(* Logix 5000 project; controller AMCI_3204_generic_sample_RSLogix_V28 vendor 1 type 14 code 92 rev 28.11; software revision 28.00 *)

TASK MainTask (continuous, watchdog 500 ms) : MainProgram

MODULES
   Local : vendor 1 type 14 code 92 (ICP 0, rev 28.11)
      AMCI_3204 : vendor 1 type 0 code 15 (ICP 4, rev 1.1, Output RPI 5 ms)
           Local:4:O.Data[10]   // AMCI 3204 channel 3 command word
           Local:4:O.Data[15]   // AMCI 3204 channel 4 command word
           Local:4:O.Data[0]   // AMCI 3204 channel 1 command word
           Local:4:O.Data[5]   // AMCI 3204 channel 2 command word
           Local:4:I.Data[0].0   // Set when 3204 channel 1 CW motion occurring
           Local:4:I.Data[0].1   // set when 3204 channel 1 CCW motion is occurring
           Local:4:I.Data[0].7   // AMCI 3204 channel 1 move complete bit
           Local:4:I.Data[1]   // AMCI 3202 ch 1 current position data
           Local:4:I.Data[0].28   // Set when AMCI 3204 ch 1 is disabled
           Local:4:I.Data[0].10   // AMCI 3204 ch 1 position invalid bit
           Local:4:I.Data[0].13   // Set when AMCI 3204 ch 1 has a configuration error
           Local:4:I.Data[0].31   // AMCI 3204 ch 1 mode bit 1=config mode 0=command mode
END_MODULES

VAR_GLOBAL   (* controller tags *)
   blend_data_3204_ch1 : DINT[52];
        [12]   // Segment 3 Acceleration or Deceleration
        [11]   // Segment 3 speed
        [9]   // Segment 2 Acceleration or Deceleration
        [1]   // Number of Segments
        [3]   // Final Segment's Deceleration Value and Type
        [13]   // Segment 4 length
        [15]   // Segment 4 Acceleration or Deceleration
        [17]   // Segment 5 speed
        [5]   // Segment 1 speed
        [7]   // Segment 2 length
        [10]   // Segment 3 length
        [14]   // Segment 4 speed
        [16]   // Segment 5 length
        [18]   // Segment 5 Acceleraiton or Deceleration
        [0]   // channel number (1 or 2)
        [2]   // Acceleration Type
        [4]   // Segment 1 length
        [6]   // Segment 1 Acceleration or Deceleration
        [8]   // Segment 2 speed
   blend_message_3204_ch1 : MESSAGE;
        .DN   // set when blend data has been programmed
        MessageParameters(ServiceCode := 16#004c, LocalElement := blend_data_3204_ch1[0], ...)
   blend_run_CW_3204 : DINT[5] := ([0] := 4096);
        [0]   // command word to run blend profile CW
   buffered_3204_data : DINT[20];
        [10].31   // AMCI 3204 ch 3 mode bit 1=config mode 0=command mode
        [0].1   // set when CCW motion is occurring on ch 1 of the AMCI 3204 module
        [10].13   // set when AMCI 3204 ch 3 has a configuration error
        [15].13   // set when AMCI 3204 ch 4 has a configuration error
        [15].31   // AMCI 3204 ch 4 mode bit 1=config mode 0=command mode
        [0].0   // set when CW motion is occurring on ch 1 of the AMCI 3204 module
        [0].7   // AMCI 3204 move complete bit
        [15].0   // set when CW motion is occurring on ch 4 of the AMCI 3204 module
        [15].1   // set when CCW motion is occurring on ch 4 of the AMCI 3204 module
        [0].28   // set when AMCI 3204 ch 1 is disabled
        [5].28   // set when AMCI 3204 ch 2 is disabled
        [10].28   // Set when 3204 channel 3 is disabled
        [15].28   // Set when 3204 channel 4 is disabled
        [5].0   // set when CW motion is occurring on ch 2 of the AMCI 3204 module
        [5].1   // set when CCW motion is occurring on ch 2 of the AMCI 3204 module
        [10].0   // set when CW motion is occurring on ch 3 of the AMCI 3204 module
        [0].10   // AMCI 3204 ch 1 position invalid bit
        [10].1   // set when CCW motion is occurring on ch 3 of the AMCI 3204 module
        [0].13   // set when AMCI 3204 ch 1 has a configuration error
        [0].31   // AMCI 3204 ch 1 mode bit 1=config mode 0=command mode
        [5].13   // set when AMCI 3204 ch 2 has a configuration error
        [5].31   // AMCI 3204 ch 2 mode bit 1=config mode 0=command mode
   CCW_manual_move_3204_ch1 : DINT[5] := ([0] := 256, [2] := 2200, [3] := 10000, [4] := 10000);
   ch1_manual_move_occurring_CCW : BOOL;
   ch1_manual_move_occurring_CW : BOOL;
   ch2_manual_move_occurring_CCW : BOOL;
   ch2_manual_move_occurring_CW : BOOL;
   ch3_manual_move_occurring_CCW : BOOL;
   ch3_manual_move_occurring_CW : BOOL;
   ch4_manual_move_occurring_CCW : BOOL;
   ch4_manual_move_occurring_CW : BOOL;
   comment : INT;
   configure_3204_ch1 : DINT[5] := ([0] := -2146500561, [1] := 100);
        [1]   // starting speed
        [0]   // configuration word
   configure_3204_ch2 : DINT[5] := ([0] := -2146500561, [1] := 100);
        [1]   // starting speed
        [0]   // configuration word
   configure_3204_ch3 : DINT[5] := ([0] := -2146500561, [1] := 100);
        [0]   // configuration word
        [1]   // starting speed
   configure_3204_ch4 : DINT[5] := ([0] := -2146500561, [1] := 100);
        [0]   // configuration word
        [1]   // starting speed
   CW_manual_move_3204_ch1 : DINT[5] := ([0] := 128, [2] := 1500, [3] := 10000, [4] := 10000);
   CW_manual_move_3204_ch2 : DINT[5] := ([0] := 128, [2] := 1500, [3] := 10000, [4] := 10000);
   CW_manual_move_3204_ch3 : DINT[5] := ([0] := 128, [2] := 1500, [3] := 10000, [4] := 10000);
   CW_manual_move_3204_ch4 : DINT[5] := ([0] := 128, [2] := 1500, [3] := 10000, [4] := 10000);
   Home_CW_3204_ch1 : DINT[5] := ([0] := 32, [2] := 1000, [3] := 10000, [4] := 10000);
   one_shot : INT;
   preset_3204_ch1 : DINT[5] := ([0] := 512);
        [0]   // preset current position command word
   Relative_move_3204_ch1 : DINT[5] := ([0] := 2, [1] := 5000, [2] := 2000, [3] := 10000, [4] := 10000);
        [0]   // relative move command word
        [1]   // distance in pulses
        [2]   // speed in pulses/sec
        [4]   // deceleration in pulses/sec/sec
        [3]   // acceleration in pulses/sec/sec
   Relative_move_3204_ch2 : DINT[5] := ([0] := 2, [1] := 5000, [2] := 2000, [3] := 10000, [4] := 10000);
        [1]   // distance in pulses
        [3]   // acceleration in pulses/sec/sec
        [4]   // deceleration in pulses/sec/sec
        [2]   // speed in pulses/sec
        [0]   // relative move command word
   Relative_move_3204_ch3 : DINT[5] := ([0] := 2, [1] := 5000, [2] := 2000, [3] := 10000, [4] := 10000);
        [1]   // distance in pulses
        [2]   // speed in pulses/sec
        [4]   // deceleration in pulses/sec/sec
        [3]   // acceleration in pulses/sec/sec
        [0]   // relative move command word
   Relative_move_3204_ch4 : DINT[5] := ([0] := 2, [1] := 5000, [2] := 2000, [3] := 10000, [4] := 10000);
        [1]   // distance in pulses
        [2]   // speed in pulses/sec
        [4]   // deceleration in pulses/sec/sec
        [3]   // acceleration in pulses/sec/sec
        [0]   // relative move command word
   Reset_errors_3204 : DINT[5] := ([0] := 2048);
   run_3204_ch1 : INT;   // 1=run relative move 2=CW Manual Move 3=CCW Manual Move 4=Reset Errors 5=Home CW 6=Preset 7=Program Blend 8=Run Blend CW
   run_3204_ch2 : INT;   // 1=run relative move 2=CW Manual Move 3=CCW Manual Move 4=Reset Errors 5=Home CW 6=Preset 7=Program Blend 8=Run Blend CW
   run_3204_ch3 : INT;   // 1=run relative move 2=CW Manual Move 3=CCW Manual Move 4=Reset Errors 5=Home CW 6=Preset 7=Program Blend 8=Run Blend CW
   run_3204_ch4 : INT;   // 1=run relative move 2=CW Manual Move 3=CCW Manual Move 4=Reset Errors 5=Home CW 6=Preset 7=Program Blend 8=Run Blend CW
END_VAR

PROGRAM MainProgram   (* main routine MainRoutine *)

ROUTINE Channel_1_3204   (* ladder *)
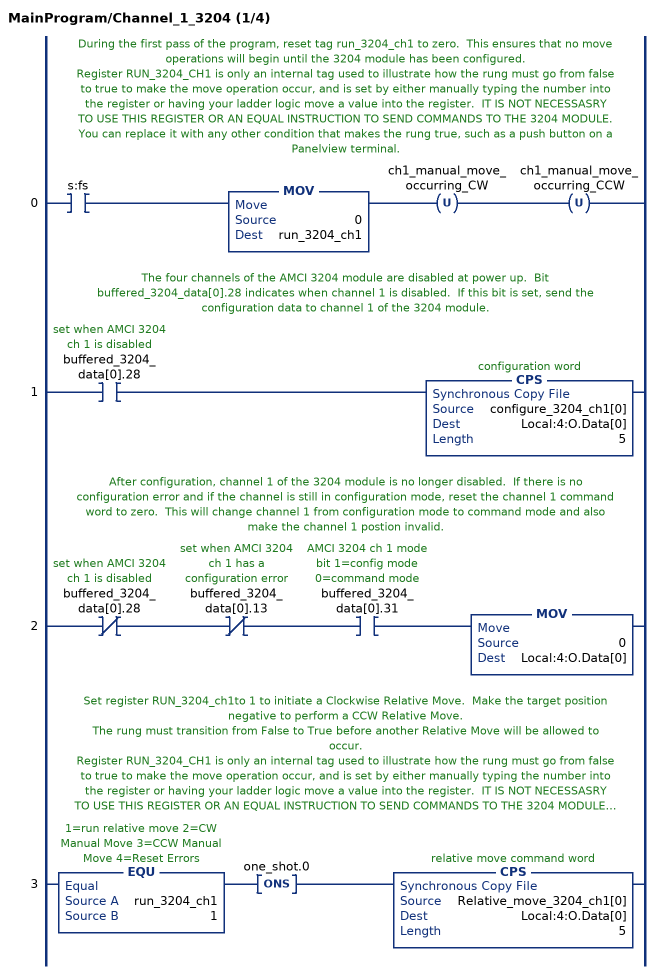
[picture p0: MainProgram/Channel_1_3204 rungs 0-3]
   // During the first pass of the program, reset tag run_3204_ch1 to zero.  This ensures that no move operations will begin until the 3204 module has been configured.
   // Register RUN_3204_CH1 is only an internal tag used to illustrate how the rung must go from false to true to make the move operation occur, and is set by either manually typing the number into the register or having your ladder logic move a value into the register.  IT IS NOT NECESSASRY TO USE THIS REGISTER OR AN EQUAL INSTRUCTION TO SEND COMMANDS TO THE 3204 MODULE.  You can replace it with any other condition that makes the rung true, such as a push button on a Panelview terminal.
   0: XIC(s:fs)MOV(0,run_3204_ch1)OTU(ch1_manual_move_occurring_CW)OTU(ch1_manual_move_occurring_CCW);
   // The four channels of the AMCI 3204 module are disabled at power up.  Bit buffered_3204_data[0].28 indicates when channel 1 is disabled.  If this bit is set, send the configuration data to channel 1 of the 3204 module.
   1: XIC(buffered_3204_data[0].28)CPS(configure_3204_ch1[0],Local:4:O.Data[0],5);
   // After configuration, channel 1 of the 3204 module is no longer disabled.  If there is no configuration error and if the channel is still in configuration mode, reset the channel 1 command word to zero.  This will change channel 1 from configuration mode to command mode and also make the channel 1 postion invalid.
   2: XIO(buffered_3204_data[0].28)XIO(buffered_3204_data[0].13)XIC(buffered_3204_data[0].31)MOV(0,Local:4:O.Data[0]);
   // Set register RUN_3204_ch1to 1 to initiate a Clockwise Relative Move.  Make the target position negative to perform a CCW Relative Move.
   // The rung must transition from False to True before another Relative Move will be allowed to occur.
   // Register RUN_3204_CH1 is only an internal tag used to illustrate how the rung must go from false to true to make the move operation occur, and is set by either manually typing the number into the register or having your ladder logic move a value into the register.  IT IS NOT NECESSASRY TO USE THIS REGISTER OR AN EQUAL INSTRUCTION TO SEND COMMANDS TO THE 3204 MODULE.  You can replace it with any other condition that makes the rung true, such as a push button on a Panelview terminal.
   3: EQU(run_3204_ch1,1)ONS(one_shot.0)CPS(Relative_move_3204_ch1[0],Local:4:O.Data[0],5);
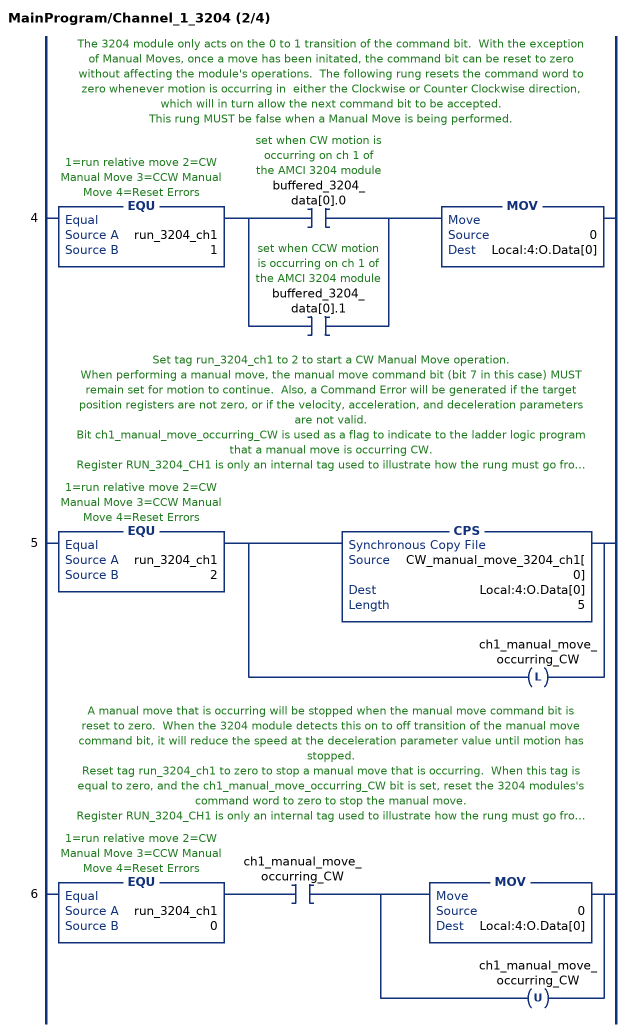
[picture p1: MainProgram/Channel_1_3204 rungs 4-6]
   // The 3204 module only acts on the 0 to 1 transition of the command bit.  With the exception of Manual Moves, once a move has been initated, the command bit can be reset to zero without affecting the module's operations.  The following rung resets the command word to zero whenever motion is occurring in  either the Clockwise or Counter Clockwise direction, which will in turn allow the next command bit to be accepted.
   // This rung MUST be false when a Manual Move is being performed.
   4: EQU(run_3204_ch1,1)[XIC(buffered_3204_data[0].0) ,XIC(buffered_3204_data[0].1) ]MOV(0,Local:4:O.Data[0]);
   // Set tag run_3204_ch1 to 2 to start a CW Manual Move operation.
   // When performing a manual move, the manual move command bit (bit 7 in this case) MUST remain set for motion to continue.  Also, a Command Error will be generated if the target position registers are not zero, or if the velocity, acceleration, and deceleration parameters are not valid.
   // Bit ch1_manual_move_occurring_CW is used as a flag to indicate to the ladder logic program that a manual move is occurring CW.
   // Register RUN_3204_CH1 is only an internal tag used to illustrate how the rung must go from false to true to make the move operation occur, and is set by either manually typing the number into the register or having your ladder logic move a value into the register.  IT IS NOT NECESSASRY TO USE THIS REGISTER OR AN EQUAL INSTRUCTION TO SEND COMMANDS TO THE 3204 MODULE.  You can replace it with any other condition that makes the rung true, such as a push button on a Panelview terminal.
   5: EQU(run_3204_ch1,2)[CPS(CW_manual_move_3204_ch1[0],Local:4:O.Data[0],5) ,OTL(ch1_manual_move_occurring_CW) ];
   // A manual move that is occurring will be stopped when the manual move command bit is reset to zero.  When the 3204 module detects this on to off transition of the manual move command bit, it will reduce the speed at the deceleration parameter value until motion has stopped.
   // Reset tag run_3204_ch1 to zero to stop a manual move that is occurring.  When this tag is equal to zero, and the ch1_manual_move_occurring_CW bit is set, reset the 3204 modules's command word to zero to stop the manual move.
   // Register RUN_3204_CH1 is only an internal tag used to illustrate how the rung must go from false to true to make the move operation occur, and is set by either manually typing the number into the register or having your ladder logic move a value into the register.  IT IS NOT NECESSASRY TO USE THIS REGISTER OR AN EQUAL INSTRUCTION TO SEND COMMANDS TO THE 3204 MODULE.  You can replace it with any other condition that makes the rung true, such as a push button on a Panelview terminal.
   6: EQU(run_3204_ch1,0)XIC(ch1_manual_move_occurring_CW)[MOV(0,Local:4:O.Data[0]) ,OTU(ch1_manual_move_occurring_CW) ];
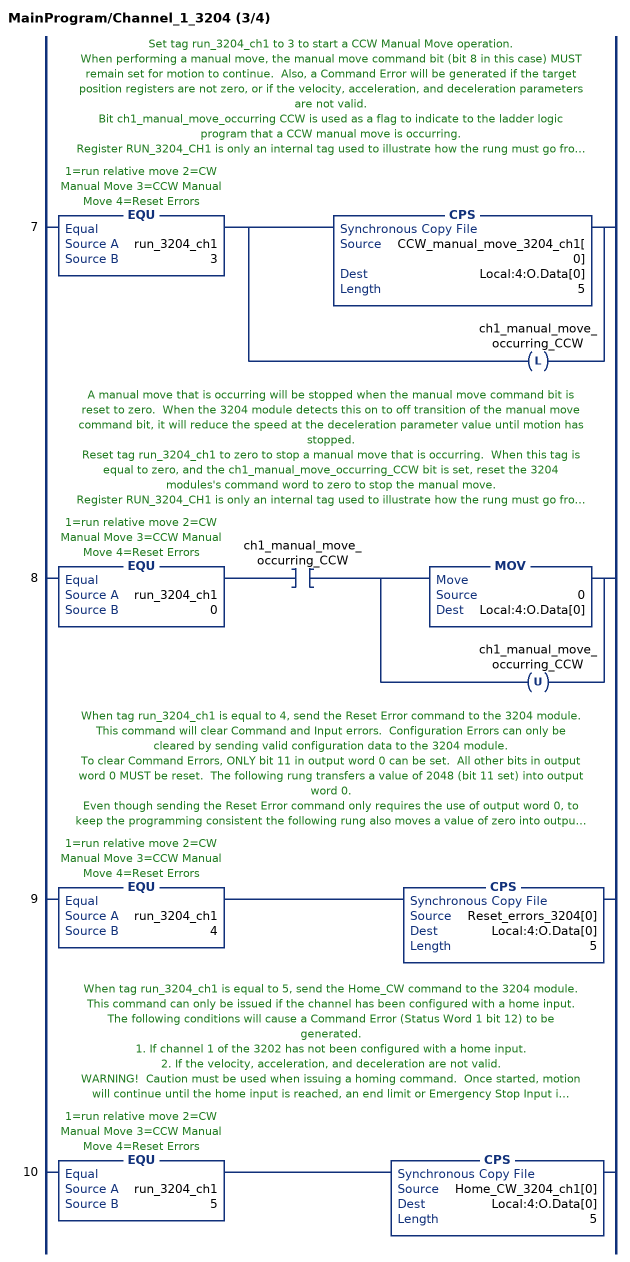
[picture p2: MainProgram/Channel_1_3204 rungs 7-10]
   // Set tag run_3204_ch1 to 3 to start a CCW Manual Move operation.
   // When performing a manual move, the manual move command bit (bit 8 in this case) MUST remain set for motion to continue.  Also, a Command Error will be generated if the target position registers are not zero, or if the velocity, acceleration, and deceleration parameters are not valid.
   // Bit ch1_manual_move_occurring CCW is used as a flag to indicate to the ladder logic program that a CCW manual move is occurring.
   // Register RUN_3204_CH1 is only an internal tag used to illustrate how the rung must go from false to true to make the move operation occur, and is set by either manually typing the number into the register or having your ladder logic move a value into the register.  IT IS NOT NECESSASRY TO USE THIS REGISTER OR AN EQUAL INSTRUCTION TO SEND COMMANDS TO THE 3204 MODULE.  You can replace it with any other condition that makes the rung true, such as a push button on a Panelview terminal.
   7: EQU(run_3204_ch1,3)[CPS(CCW_manual_move_3204_ch1[0],Local:4:O.Data[0],5) ,OTL(ch1_manual_move_occurring_CCW) ];
   // A manual move that is occurring will be stopped when the manual move command bit is reset to zero.  When the 3204 module detects this on to off transition of the manual move command bit, it will reduce the speed at the deceleration parameter value until motion has stopped.
   // Reset tag run_3204_ch1 to zero to stop a manual move that is occurring.  When this tag is equal to zero, and the ch1_manual_move_occurring_CCW bit is set, reset the 3204 modules's command word to zero to stop the manual move.
   // Register RUN_3204_CH1 is only an internal tag used to illustrate how the rung must go from false to true to make the move operation occur, and is set by either manually typing the number into the register or having your ladder logic move a value into the register.  IT IS NOT NECESSASRY TO USE THIS REGISTER OR AN EQUAL INSTRUCTION TO SEND COMMANDS TO THE 3204 MODULE.  You can replace it with any other condition that makes the rung true, such as a push button on a Panelview terminal.
   8: EQU(run_3204_ch1,0)XIC(ch1_manual_move_occurring_CCW)[MOV(0,Local:4:O.Data[0]) ,OTU(ch1_manual_move_occurring_CCW) ];
   // When tag run_3204_ch1 is equal to 4, send the Reset Error command to the 3204 module.  This command will clear Command and Input errors.  Configuration Errors can only be cleared by sending valid configuration data to the 3204 module.
   // To clear Command Errors, ONLY bit 11 in output word 0 can be set.  All other bits in output word 0 MUST be reset.  The following rung transfers a value of 2048 (bit 11 set) into output word 0.
   // Even though sending the Reset Error command only requires the use of output word 0, to keep the programming consistent the following rung also moves a value of zero into output words 1 through 4.
   // Register RUN_3204_CH1 is only an internal tag used to illustrate how the rung must go from false to true to make the move operation occur, and is set by either manually typing the number into the register or having your ladder logic move a value into the register.  IT IS NOT NECESSASRY TO USE THIS REGISTER OR AN EQUAL INSTRUCTION TO SEND COMMANDS TO THE 3204 MODULE.  You can replace it with any other condition that makes the rung true, such as a push button on a Panelview terminal.
   9: EQU(run_3204_ch1,4)CPS(Reset_errors_3204[0],Local:4:O.Data[0],5);
   // When tag run_3204_ch1 is equal to 5, send the Home_CW command to the 3204 module.  This command can only be issued if the channel has been configured with a home input.  The following conditions will cause a Command Error (Status Word 1 bit 12) to be generated.
   // 1. If channel 1 of the 3202 has not been configured with a home input.
   // 2. If the velocity, acceleration, and deceleration are not valid.
   // WARNING!  Caution must be used when issuing a homing command.  Once started, motion will continue until the home input is reached, an end limit or Emergency Stop Input in reached, or the Immediate Stop Command is issued.  Resetting the command word to zero WILL NOT STOP a home operation.
   // Register RUN_3204_CH1 is only an internal tag used to illustrate how the rung must go from false to true to make the move operation occur, and is set by either manually typing the number into the register or having your ladder logic move a value into the register.  IT IS NOT NECESSASRY TO USE THIS REGISTER OR AN EQUAL INSTRUCTION TO SEND COMMANDS TO THE 3204 MODULE.  You can replace it with any other condition that makes the rung true, such as a push button on a Panelview terminal.
   10: EQU(run_3204_ch1,5)CPS(Home_CW_3204_ch1[0],Local:4:O.Data[0],5);
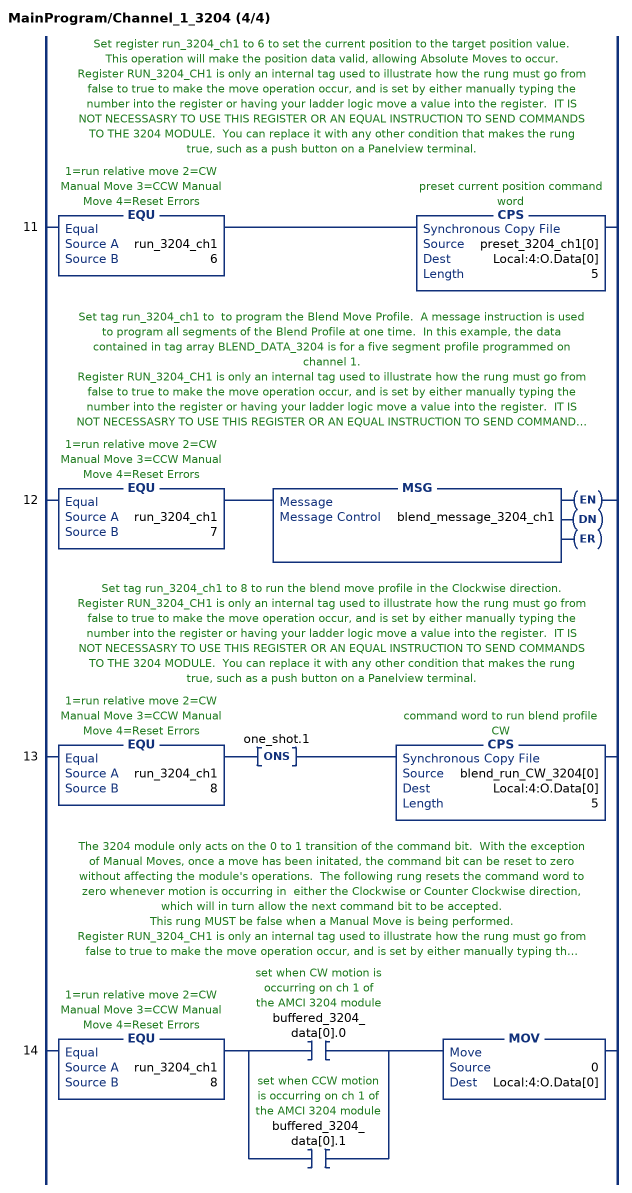
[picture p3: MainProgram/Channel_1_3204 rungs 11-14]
   // Set register run_3204_ch1 to 6 to set the current position to the target position value.
   // This operation will make the position data valid, allowing Absolute Moves to occur.
   // Register RUN_3204_CH1 is only an internal tag used to illustrate how the rung must go from false to true to make the move operation occur, and is set by either manually typing the number into the register or having your ladder logic move a value into the register.  IT IS NOT NECESSASRY TO USE THIS REGISTER OR AN EQUAL INSTRUCTION TO SEND COMMANDS TO THE 3204 MODULE.  You can replace it with any other condition that makes the rung true, such as a push button on a Panelview terminal.
   11: EQU(run_3204_ch1,6)CPS(preset_3204_ch1[0],Local:4:O.Data[0],5);
   // Set tag run_3204_ch1 to  to program the Blend Move Profile.  A message instruction is used to program all segments of the Blend Profile at one time.  In this example, the data contained in tag array BLEND_DATA_3204 is for a five segment profile programmed on channel 1.
   // Register RUN_3204_CH1 is only an internal tag used to illustrate how the rung must go from false to true to make the move operation occur, and is set by either manually typing the number into the register or having your ladder logic move a value into the register.  IT IS NOT NECESSASRY TO USE THIS REGISTER OR AN EQUAL INSTRUCTION TO SEND COMMANDS TO THE 3204 MODULE.  You can replace it with any other condition that makes the rung true, such as a push button on a Panelview terminal.
   12: EQU(run_3204_ch1,7)MSG(blend_message_3204_ch1);
   // Set tag run_3204_ch1 to 8 to run the blend move profile in the Clockwise direction.
   // Register RUN_3204_CH1 is only an internal tag used to illustrate how the rung must go from false to true to make the move operation occur, and is set by either manually typing the number into the register or having your ladder logic move a value into the register.  IT IS NOT NECESSASRY TO USE THIS REGISTER OR AN EQUAL INSTRUCTION TO SEND COMMANDS TO THE 3204 MODULE.  You can replace it with any other condition that makes the rung true, such as a push button on a Panelview terminal.
   13: EQU(run_3204_ch1,8)ONS(one_shot.1)CPS(blend_run_CW_3204[0],Local:4:O.Data[0],5);
   // The 3204 module only acts on the 0 to 1 transition of the command bit.  With the exception of Manual Moves, once a move has been initated, the command bit can be reset to zero without affecting the module's operations.  The following rung resets the command word to zero whenever motion is occurring in  either the Clockwise or Counter Clockwise direction, which will in turn allow the next command bit to be accepted.
   // This rung MUST be false when a Manual Move is being performed.
   // Register RUN_3204_CH1 is only an internal tag used to illustrate how the rung must go from false to true to make the move operation occur, and is set by either manually typing the number into the register or having your ladder logic move a value into the register.  IT IS NOT NECESSASRY TO USE THIS REGISTER OR AN EQUAL INSTRUCTION TO SEND COMMANDS TO THE 3204 MODULE.  You can replace it with any other condition that makes the rung true, such as a push button on a Panelview terminal.
   14: EQU(run_3204_ch1,8)[XIC(buffered_3204_data[0].0) ,XIC(buffered_3204_data[0].1) ]MOV(0,Local:4:O.Data[0]);
END_ROUTINE

ROUTINE Channel_2_3204   (* ladder *)
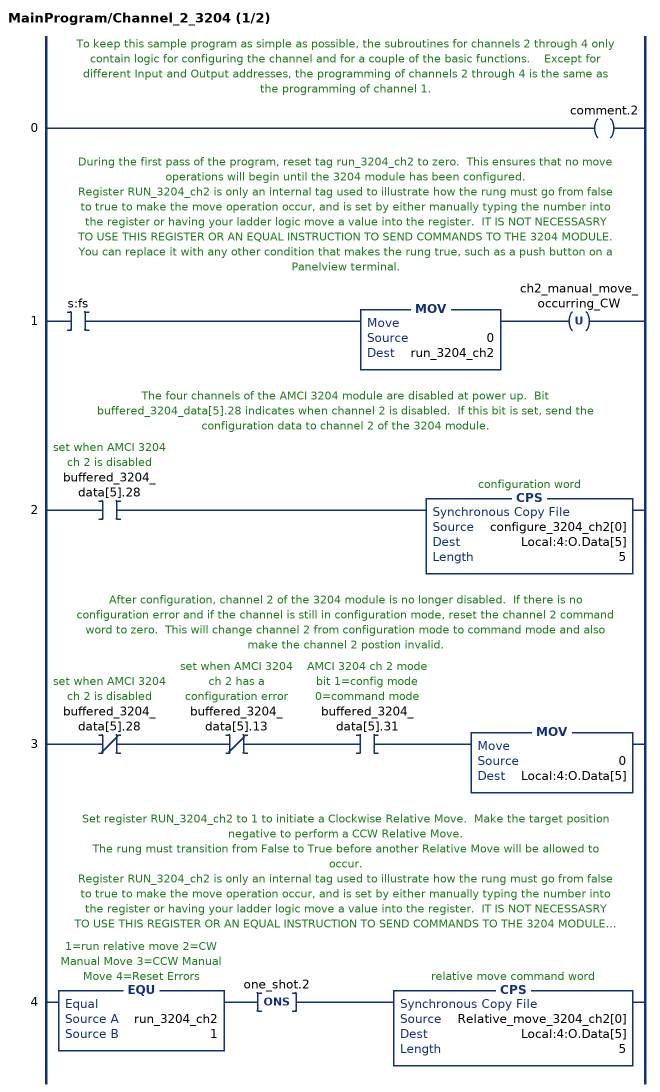
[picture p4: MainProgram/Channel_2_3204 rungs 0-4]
   // To keep this sample program as simple as possible, the subroutines for channels 2 through 4 only contain logic for configuring the channel and for a couple of the basic functions.    Except for different Input and Output addresses, the programming of channels 2 through 4 is the same as the programming of channel 1.
   0: OTE(comment.2);
   // During the first pass of the program, reset tag run_3204_ch2 to zero.  This ensures that no move operations will begin until the 3204 module has been configured.
   // Register RUN_3204_ch2 is only an internal tag used to illustrate how the rung must go from false to true to make the move operation occur, and is set by either manually typing the number into the register or having your ladder logic move a value into the register.  IT IS NOT NECESSASRY TO USE THIS REGISTER OR AN EQUAL INSTRUCTION TO SEND COMMANDS TO THE 3204 MODULE.  You can replace it with any other condition that makes the rung true, such as a push button on a Panelview terminal.
   1: XIC(s:fs)MOV(0,run_3204_ch2)OTU(ch2_manual_move_occurring_CW);
   // The four channels of the AMCI 3204 module are disabled at power up.  Bit buffered_3204_data[5].28 indicates when channel 2 is disabled.  If this bit is set, send the configuration data to channel 2 of the 3204 module.
   2: XIC(buffered_3204_data[5].28)CPS(configure_3204_ch2[0],Local:4:O.Data[5],5);
   // After configuration, channel 2 of the 3204 module is no longer disabled.  If there is no configuration error and if the channel is still in configuration mode, reset the channel 2 command word to zero.  This will change channel 2 from configuration mode to command mode and also make the channel 2 postion invalid.
   3: XIO(buffered_3204_data[5].28)XIO(buffered_3204_data[5].13)XIC(buffered_3204_data[5].31)MOV(0,Local:4:O.Data[5]);
   // Set register RUN_3204_ch2 to 1 to initiate a Clockwise Relative Move.  Make the target position negative to perform a CCW Relative Move.
   // The rung must transition from False to True before another Relative Move will be allowed to occur.
   // Register RUN_3204_ch2 is only an internal tag used to illustrate how the rung must go from false to true to make the move operation occur, and is set by either manually typing the number into the register or having your ladder logic move a value into the register.  IT IS NOT NECESSASRY TO USE THIS REGISTER OR AN EQUAL INSTRUCTION TO SEND COMMANDS TO THE 3204 MODULE.  You can replace it with any other condition that makes the rung true, such as a push button on a Panelview terminal.
   4: EQU(run_3204_ch2,1)ONS(one_shot.2)CPS(Relative_move_3204_ch2[0],Local:4:O.Data[5],5);
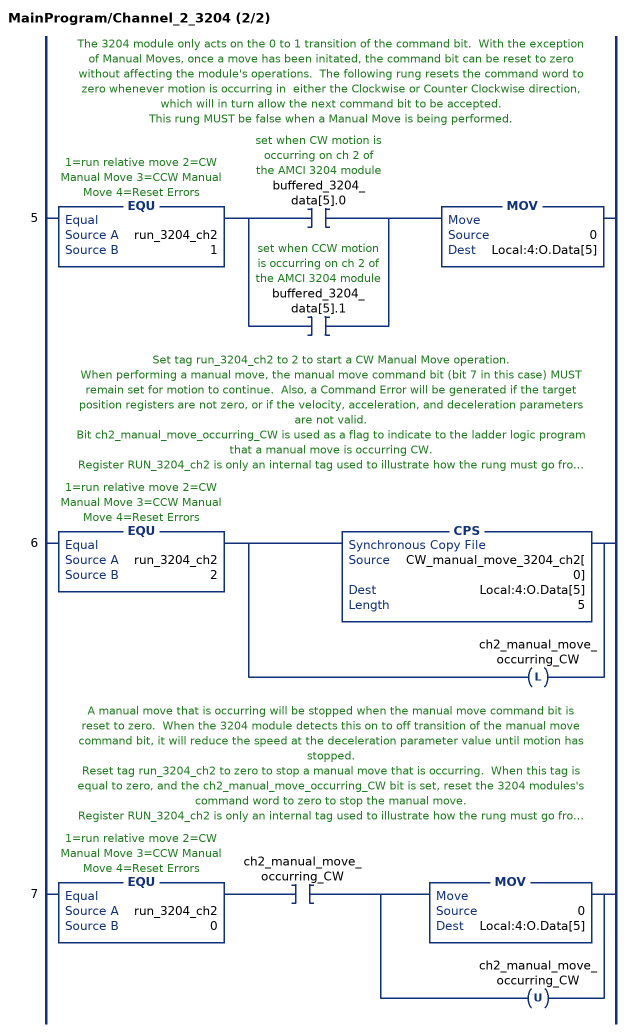
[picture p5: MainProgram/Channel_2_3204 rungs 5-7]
   // The 3204 module only acts on the 0 to 1 transition of the command bit.  With the exception of Manual Moves, once a move has been initated, the command bit can be reset to zero without affecting the module's operations.  The following rung resets the command word to zero whenever motion is occurring in  either the Clockwise or Counter Clockwise direction, which will in turn allow the next command bit to be accepted.
   // This rung MUST be false when a Manual Move is being performed.
   5: EQU(run_3204_ch2,1)[XIC(buffered_3204_data[5].0) ,XIC(buffered_3204_data[5].1) ]MOV(0,Local:4:O.Data[5]);
   // Set tag run_3204_ch2 to 2 to start a CW Manual Move operation.
   // When performing a manual move, the manual move command bit (bit 7 in this case) MUST remain set for motion to continue.  Also, a Command Error will be generated if the target position registers are not zero, or if the velocity, acceleration, and deceleration parameters are not valid.
   // Bit ch2_manual_move_occurring_CW is used as a flag to indicate to the ladder logic program that a manual move is occurring CW.
   // Register RUN_3204_ch2 is only an internal tag used to illustrate how the rung must go from false to true to make the move operation occur, and is set by either manually typing the number into the register or having your ladder logic move a value into the register.  IT IS NOT NECESSASRY TO USE THIS REGISTER OR AN EQUAL INSTRUCTION TO SEND COMMANDS TO THE 3204 MODULE.  You can replace it with any other condition that makes the rung true, such as a push button on a Panelview terminal.
   6: EQU(run_3204_ch2,2)[CPS(CW_manual_move_3204_ch2[0],Local:4:O.Data[5],5) ,OTL(ch2_manual_move_occurring_CW) ];
   // A manual move that is occurring will be stopped when the manual move command bit is reset to zero.  When the 3204 module detects this on to off transition of the manual move command bit, it will reduce the speed at the deceleration parameter value until motion has stopped.
   // Reset tag run_3204_ch2 to zero to stop a manual move that is occurring.  When this tag is equal to zero, and the ch2_manual_move_occurring_CW bit is set, reset the 3204 modules's command word to zero to stop the manual move.
   // Register RUN_3204_ch2 is only an internal tag used to illustrate how the rung must go from false to true to make the move operation occur, and is set by either manually typing the number into the register or having your ladder logic move a value into the register.  IT IS NOT NECESSASRY TO USE THIS REGISTER OR AN EQUAL INSTRUCTION TO SEND COMMANDS TO THE 3204 MODULE.  You can replace it with any other condition that makes the rung true, such as a push button on a Panelview terminal.
   7: EQU(run_3204_ch2,0)XIC(ch2_manual_move_occurring_CW)[MOV(0,Local:4:O.Data[5]) ,OTU(ch2_manual_move_occurring_CW) ];
END_ROUTINE

ROUTINE Channel_3_3204   (* ladder *)
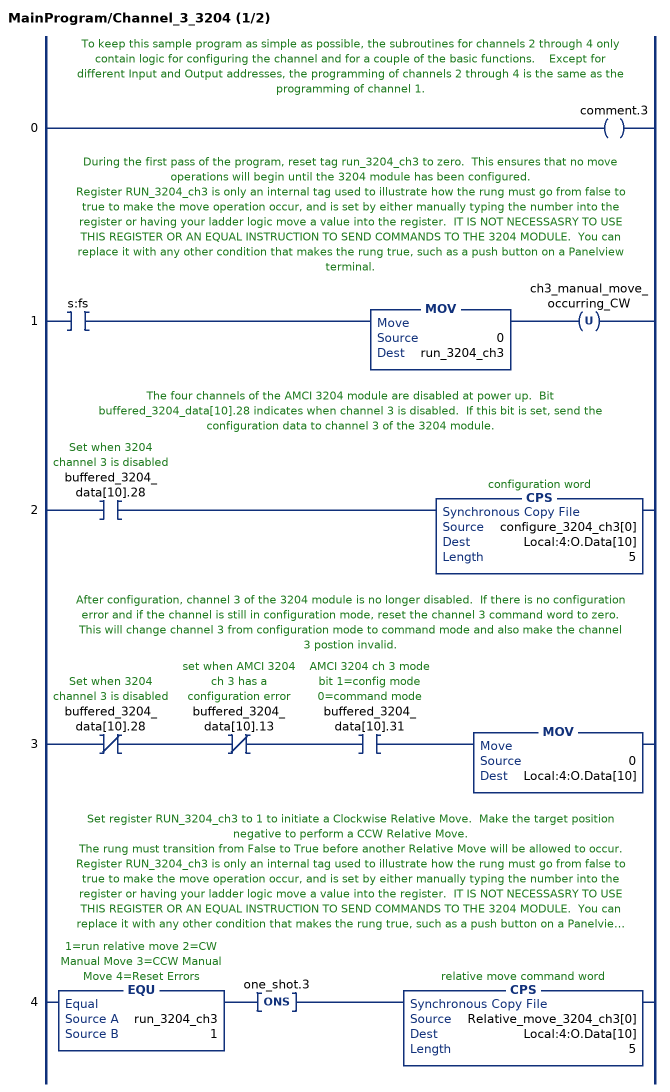
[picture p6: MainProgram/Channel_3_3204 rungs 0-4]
   // To keep this sample program as simple as possible, the subroutines for channels 2 through 4 only contain logic for configuring the channel and for a couple of the basic functions.    Except for different Input and Output addresses, the programming of channels 2 through 4 is the same as the programming of channel 1.
   0: OTE(comment.3);
   // During the first pass of the program, reset tag run_3204_ch3 to zero.  This ensures that no move operations will begin until the 3204 module has been configured.
   // Register RUN_3204_ch3 is only an internal tag used to illustrate how the rung must go from false to true to make the move operation occur, and is set by either manually typing the number into the register or having your ladder logic move a value into the register.  IT IS NOT NECESSASRY TO USE THIS REGISTER OR AN EQUAL INSTRUCTION TO SEND COMMANDS TO THE 3204 MODULE.  You can replace it with any other condition that makes the rung true, such as a push button on a Panelview terminal.
   1: XIC(s:fs)MOV(0,run_3204_ch3)OTU(ch3_manual_move_occurring_CW);
   // The four channels of the AMCI 3204 module are disabled at power up.  Bit buffered_3204_data[10].28 indicates when channel 3 is disabled.  If this bit is set, send the configuration data to channel 3 of the 3204 module.
   2: XIC(buffered_3204_data[10].28)CPS(configure_3204_ch3[0],Local:4:O.Data[10],5);
   // After configuration, channel 3 of the 3204 module is no longer disabled.  If there is no configuration error and if the channel is still in configuration mode, reset the channel 3 command word to zero.  This will change channel 3 from configuration mode to command mode and also make the channel 3 postion invalid.
   3: XIO(buffered_3204_data[10].28)XIO(buffered_3204_data[10].13)XIC(buffered_3204_data[10].31)MOV(0,Local:4:O.Data[10]);
   // Set register RUN_3204_ch3 to 1 to initiate a Clockwise Relative Move.  Make the target position negative to perform a CCW Relative Move.
   // The rung must transition from False to True before another Relative Move will be allowed to occur.
   // Register RUN_3204_ch3 is only an internal tag used to illustrate how the rung must go from false to true to make the move operation occur, and is set by either manually typing the number into the register or having your ladder logic move a value into the register.  IT IS NOT NECESSASRY TO USE THIS REGISTER OR AN EQUAL INSTRUCTION TO SEND COMMANDS TO THE 3204 MODULE.  You can replace it with any other condition that makes the rung true, such as a push button on a Panelview terminal.
   4: EQU(run_3204_ch3,1)ONS(one_shot.3)CPS(Relative_move_3204_ch3[0],Local:4:O.Data[10],5);
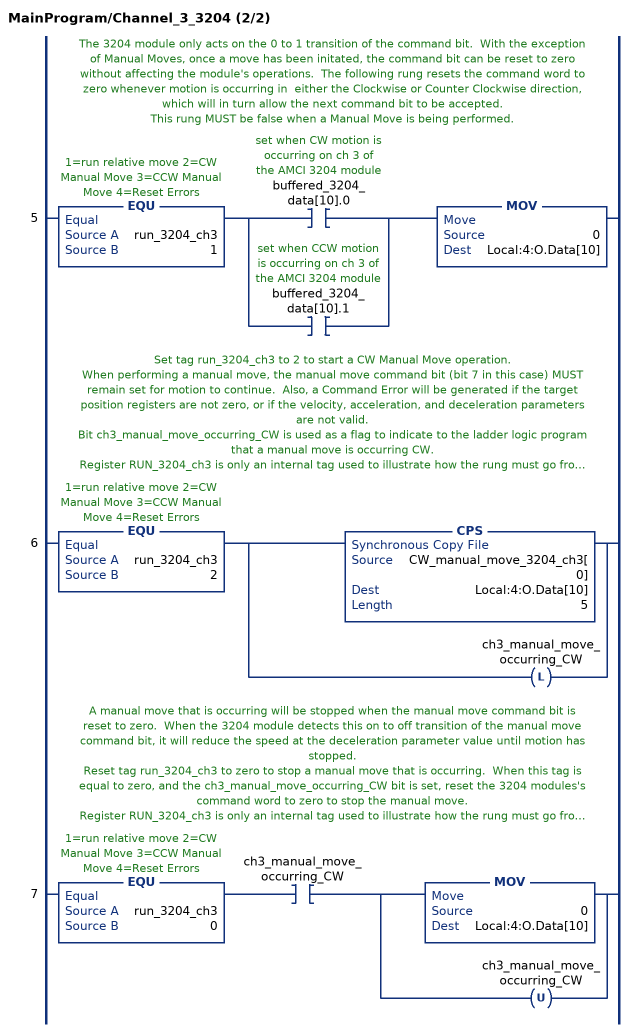
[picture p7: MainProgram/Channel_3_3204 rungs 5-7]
   // The 3204 module only acts on the 0 to 1 transition of the command bit.  With the exception of Manual Moves, once a move has been initated, the command bit can be reset to zero without affecting the module's operations.  The following rung resets the command word to zero whenever motion is occurring in  either the Clockwise or Counter Clockwise direction, which will in turn allow the next command bit to be accepted.
   // This rung MUST be false when a Manual Move is being performed.
   5: EQU(run_3204_ch3,1)[XIC(buffered_3204_data[10].0) ,XIC(buffered_3204_data[10].1) ]MOV(0,Local:4:O.Data[10]);
   // Set tag run_3204_ch3 to 2 to start a CW Manual Move operation.
   // When performing a manual move, the manual move command bit (bit 7 in this case) MUST remain set for motion to continue.  Also, a Command Error will be generated if the target position registers are not zero, or if the velocity, acceleration, and deceleration parameters are not valid.
   // Bit ch3_manual_move_occurring_CW is used as a flag to indicate to the ladder logic program that a manual move is occurring CW.
   // Register RUN_3204_ch3 is only an internal tag used to illustrate how the rung must go from false to true to make the move operation occur, and is set by either manually typing the number into the register or having your ladder logic move a value into the register.  IT IS NOT NECESSASRY TO USE THIS REGISTER OR AN EQUAL INSTRUCTION TO SEND COMMANDS TO THE 3204 MODULE.  You can replace it with any other condition that makes the rung true, such as a push button on a Panelview terminal.
   6: EQU(run_3204_ch3,2)[CPS(CW_manual_move_3204_ch3[0],Local:4:O.Data[10],5) ,OTL(ch3_manual_move_occurring_CW) ];
   // A manual move that is occurring will be stopped when the manual move command bit is reset to zero.  When the 3204 module detects this on to off transition of the manual move command bit, it will reduce the speed at the deceleration parameter value until motion has stopped.
   // Reset tag run_3204_ch3 to zero to stop a manual move that is occurring.  When this tag is equal to zero, and the ch3_manual_move_occurring_CW bit is set, reset the 3204 modules's command word to zero to stop the manual move.
   // Register RUN_3204_ch3 is only an internal tag used to illustrate how the rung must go from false to true to make the move operation occur, and is set by either manually typing the number into the register or having your ladder logic move a value into the register.  IT IS NOT NECESSASRY TO USE THIS REGISTER OR AN EQUAL INSTRUCTION TO SEND COMMANDS TO THE 3204 MODULE.  You can replace it with any other condition that makes the rung true, such as a push button on a Panelview terminal.
   7: EQU(run_3204_ch3,0)XIC(ch3_manual_move_occurring_CW)[MOV(0,Local:4:O.Data[10]) ,OTU(ch3_manual_move_occurring_CW) ];
END_ROUTINE

ROUTINE Channel_4_3204   (* ladder *)
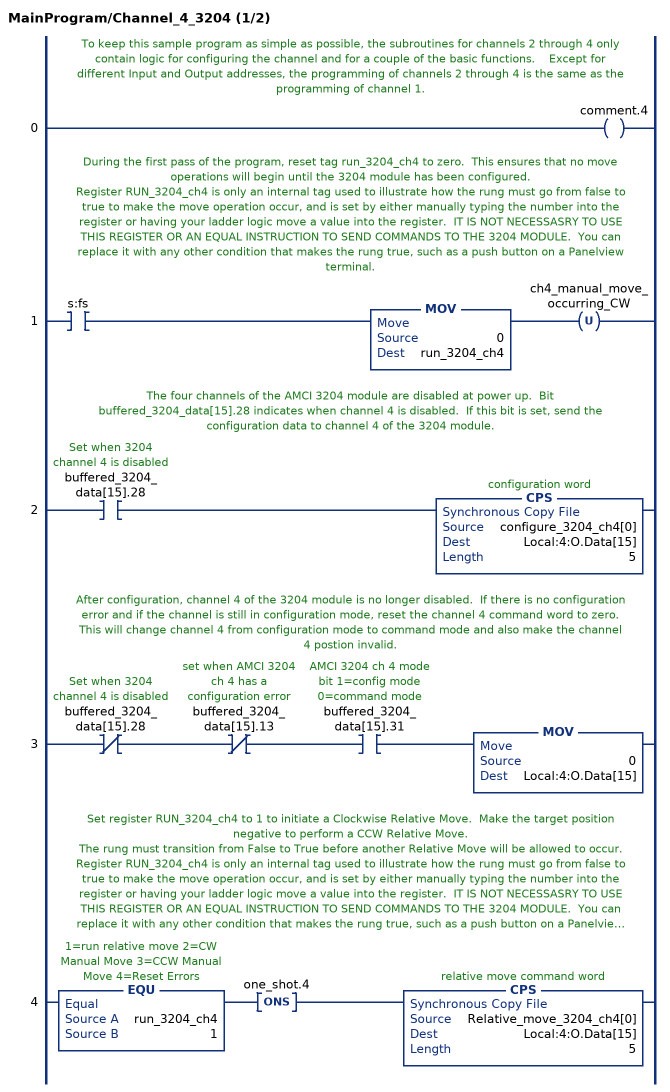
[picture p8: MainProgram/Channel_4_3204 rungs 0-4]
   // To keep this sample program as simple as possible, the subroutines for channels 2 through 4 only contain logic for configuring the channel and for a couple of the basic functions.    Except for different Input and Output addresses, the programming of channels 2 through 4 is the same as the programming of channel 1.
   0: OTE(comment.4);
   // During the first pass of the program, reset tag run_3204_ch4 to zero.  This ensures that no move operations will begin until the 3204 module has been configured.
   // Register RUN_3204_ch4 is only an internal tag used to illustrate how the rung must go from false to true to make the move operation occur, and is set by either manually typing the number into the register or having your ladder logic move a value into the register.  IT IS NOT NECESSASRY TO USE THIS REGISTER OR AN EQUAL INSTRUCTION TO SEND COMMANDS TO THE 3204 MODULE.  You can replace it with any other condition that makes the rung true, such as a push button on a Panelview terminal.
   1: XIC(s:fs)MOV(0,run_3204_ch4)OTU(ch4_manual_move_occurring_CW);
   // The four channels of the AMCI 3204 module are disabled at power up.  Bit buffered_3204_data[15].28 indicates when channel 4 is disabled.  If this bit is set, send the configuration data to channel 4 of the 3204 module.
   2: XIC(buffered_3204_data[15].28)CPS(configure_3204_ch4[0],Local:4:O.Data[15],5);
   // After configuration, channel 4 of the 3204 module is no longer disabled.  If there is no configuration error and if the channel is still in configuration mode, reset the channel 4 command word to zero.  This will change channel 4 from configuration mode to command mode and also make the channel 4 postion invalid.
   3: XIO(buffered_3204_data[15].28)XIO(buffered_3204_data[15].13)XIC(buffered_3204_data[15].31)MOV(0,Local:4:O.Data[15]);
   // Set register RUN_3204_ch4 to 1 to initiate a Clockwise Relative Move.  Make the target position negative to perform a CCW Relative Move.
   // The rung must transition from False to True before another Relative Move will be allowed to occur.
   // Register RUN_3204_ch4 is only an internal tag used to illustrate how the rung must go from false to true to make the move operation occur, and is set by either manually typing the number into the register or having your ladder logic move a value into the register.  IT IS NOT NECESSASRY TO USE THIS REGISTER OR AN EQUAL INSTRUCTION TO SEND COMMANDS TO THE 3204 MODULE.  You can replace it with any other condition that makes the rung true, such as a push button on a Panelview terminal.
   4: EQU(run_3204_ch4,1)ONS(one_shot.4)CPS(Relative_move_3204_ch4[0],Local:4:O.Data[15],5);
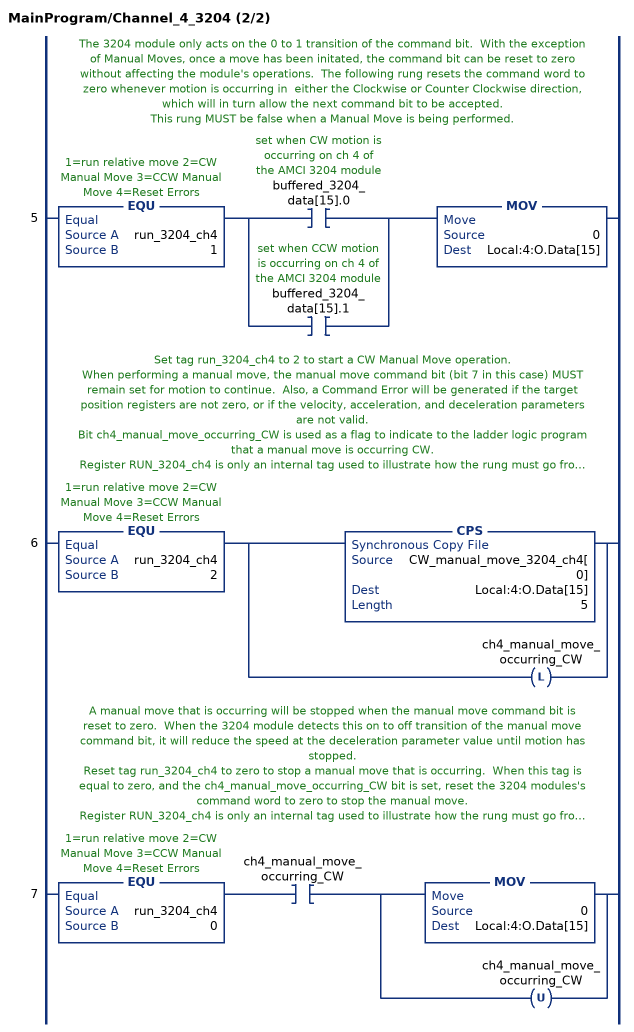
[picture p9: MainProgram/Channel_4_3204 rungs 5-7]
   // The 3204 module only acts on the 0 to 1 transition of the command bit.  With the exception of Manual Moves, once a move has been initated, the command bit can be reset to zero without affecting the module's operations.  The following rung resets the command word to zero whenever motion is occurring in  either the Clockwise or Counter Clockwise direction, which will in turn allow the next command bit to be accepted.
   // This rung MUST be false when a Manual Move is being performed.
   5: EQU(run_3204_ch4,1)[XIC(buffered_3204_data[15].0) ,XIC(buffered_3204_data[15].1) ]MOV(0,Local:4:O.Data[15]);
   // Set tag run_3204_ch4 to 2 to start a CW Manual Move operation.
   // When performing a manual move, the manual move command bit (bit 7 in this case) MUST remain set for motion to continue.  Also, a Command Error will be generated if the target position registers are not zero, or if the velocity, acceleration, and deceleration parameters are not valid.
   // Bit ch4_manual_move_occurring_CW is used as a flag to indicate to the ladder logic program that a manual move is occurring CW.
   // Register RUN_3204_ch4 is only an internal tag used to illustrate how the rung must go from false to true to make the move operation occur, and is set by either manually typing the number into the register or having your ladder logic move a value into the register.  IT IS NOT NECESSASRY TO USE THIS REGISTER OR AN EQUAL INSTRUCTION TO SEND COMMANDS TO THE 3204 MODULE.  You can replace it with any other condition that makes the rung true, such as a push button on a Panelview terminal.
   6: EQU(run_3204_ch4,2)[CPS(CW_manual_move_3204_ch4[0],Local:4:O.Data[15],5) ,OTL(ch4_manual_move_occurring_CW) ];
   // A manual move that is occurring will be stopped when the manual move command bit is reset to zero.  When the 3204 module detects this on to off transition of the manual move command bit, it will reduce the speed at the deceleration parameter value until motion has stopped.
   // Reset tag run_3204_ch4 to zero to stop a manual move that is occurring.  When this tag is equal to zero, and the ch4_manual_move_occurring_CW bit is set, reset the 3204 modules's command word to zero to stop the manual move.
   // Register RUN_3204_ch4 is only an internal tag used to illustrate how the rung must go from false to true to make the move operation occur, and is set by either manually typing the number into the register or having your ladder logic move a value into the register.  IT IS NOT NECESSASRY TO USE THIS REGISTER OR AN EQUAL INSTRUCTION TO SEND COMMANDS TO THE 3204 MODULE.  You can replace it with any other condition that makes the rung true, such as a push button on a Panelview terminal.
   7: EQU(run_3204_ch4,0)XIC(ch4_manual_move_occurring_CW)[MOV(0,Local:4:O.Data[15]) ,OTU(ch4_manual_move_occurring_CW) ];
END_ROUTINE

ROUTINE MainRoutine   (* ladder *)
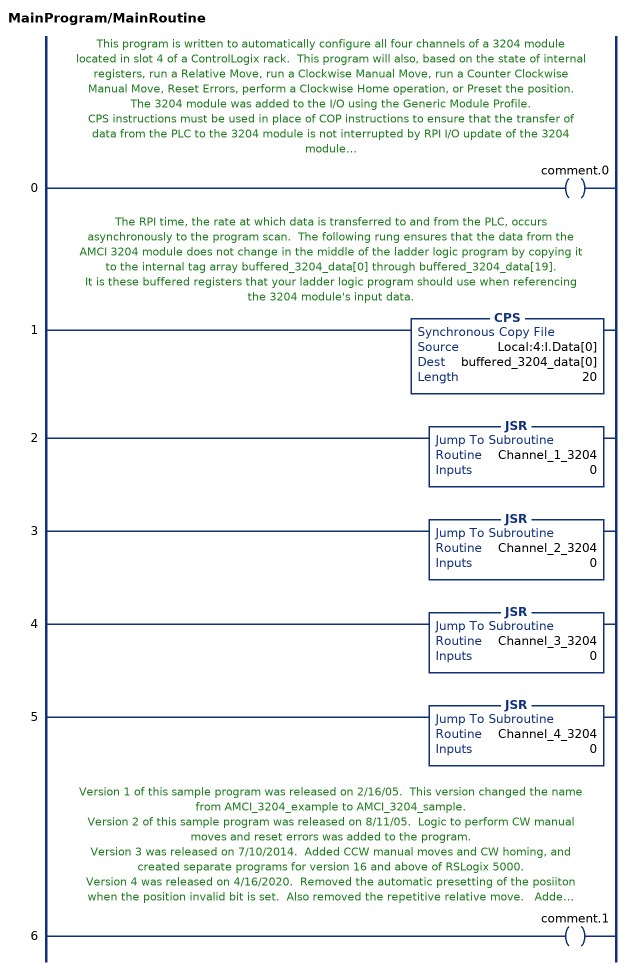
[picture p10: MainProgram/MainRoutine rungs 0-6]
   // This program is written to automatically configure all four channels of a 3204 module located in slot 4 of a ControlLogix rack.  This program will also, based on the state of internal registers, run a Relative Move, run a Clockwise Manual Move, run a Counter Clockwise Manual Move, Reset Errors, perform a Clockwise Home operation, or Preset the position.
   // The 3204 module was added to the I/O using the Generic Module Profile.
   // CPS instructions must be used in place of COP instructions to ensure that the transfer of data from the PLC to the 3204 module is not interrupted by RPI I/O update of the 3204 module.
   // To keep this sample program as simple as possible, the subroutines for channels 2 through 4 only contain logic for configuring the channel and for a couple of the basic functions.    Except for different Input and Output addresses, the programming of channels 2 through 4 is the same as the programming of channel 1.
   // This program also contains logic to program and perform blend moves.  This logic is optional and if not needed, can be deleted or ignored.
   // Registers RUN_3204_ch1 to RUN_3204_ch4 are only internal tags used to illustrate how the rung must go from false to true to make the move operation occur, and is set by either manually typing the number into the register or having your ladder logic move a value into the register.  IT IS NOT NECESSASRY TO USE these REGISTER OR AN EQUAL INSTRUCTION TO SEND COMMANDS TO THE 3204 MODULE.  You can replace it with any other condition that makes the rung true, such as a push button on a Panelview terminal.
   0: OTE(comment.0);
   // The RPI time, the rate at which data is transferred to and from the PLC, occurs asynchronously to the program scan.  The following rung ensures that the data from the AMCI 3204 module does not change in the middle of the ladder logic program by copying it to the internal tag array buffered_3204_data[0] through buffered_3204_data[19].
   // It is these buffered registers that your ladder logic program should use when referencing the 3204 module's input data.
   1: CPS(Local:4:I.Data[0],buffered_3204_data[0],20);
   2: JSR(Channel_1_3204,0);
   3: JSR(Channel_2_3204,0);
   4: JSR(Channel_3_3204,0);
   5: JSR(Channel_4_3204,0);
   // Version 1 of this sample program was released on 2/16/05.  This version changed the name from AMCI_3204_example to AMCI_3204_sample.
   // Version 2 of this sample program was released on 8/11/05.  Logic to perform CW manual moves and reset errors was added to the program.
   // Version 3 was released on 7/10/2014.  Added CCW manual moves and CW homing, and created separate programs for version 16 and above of RSLogix 5000.
   // Version 4 was released on 4/16/2020.  Removed the automatic presetting of the posiiton when the position invalid bit is set.  Also removed the repetitive relative move.   Added relative and CW Manual Moves to the channels 2 through 4 subroutines.
   6: OTE(comment.1);
END_ROUTINE
END_PROGRAM
